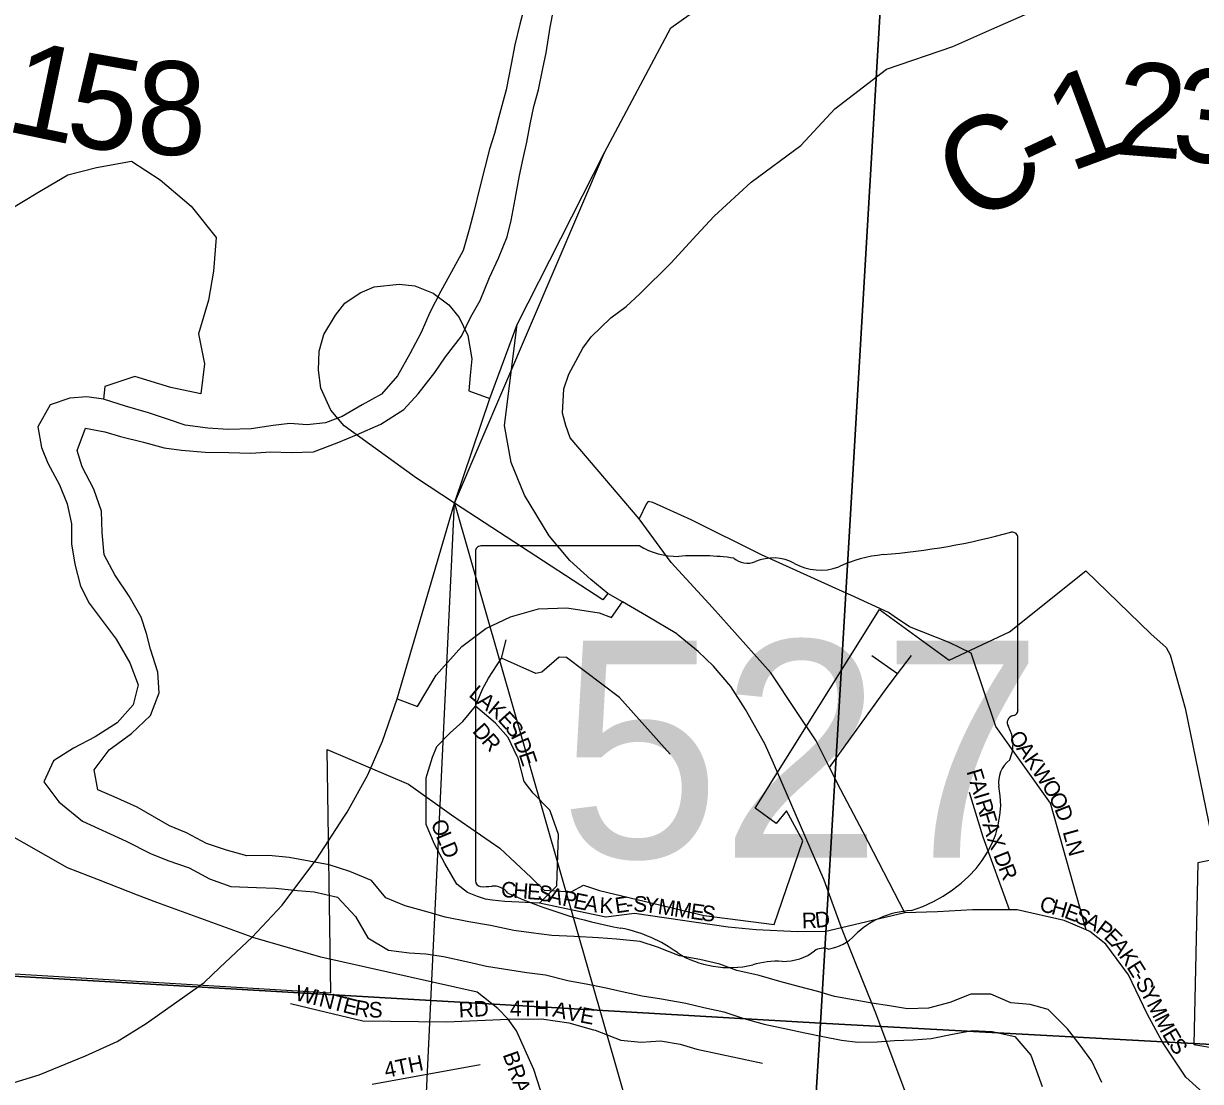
# Model space of a CAD drawing. Extents: x 0 to 34, y 0 to 22.
# Drawn here: x 4.109 to 4.825, y 15.987 to 16.63 of the extents above; entities that cross this region are included whole.
import ezdxf

# ---------------------------------------------------------------- set-up
doc = ezdxf.new("R2010")
doc.units = 0
for name, color, linetype in [('GM_P_State_Alignment', 7, 'Continuous'), ('GM_X_City_Street', 7, 'Continuous'), ('GM_X_City_Street_Text', 7, 'Continuous'), ('GM_X_Corporation', 7, 'Continuous'), ('GM_X_County_Road', 7, 'Continuous'), ('GM_X_County_Road_Text', 7, 'Continuous'), ('GM_X_Interchange_Ramps', 7, 'Continuous'), ('GM_X_Major_River', 7, 'Continuous'), ('GM_X_Minor_River', 7, 'Continuous'), ('GM_X_Section', 7, 'Continuous'), ('GM_X_State_Location', 7, 'Continuous'), ('GM_X_State_Route', 7, 'Continuous'), ('GM_X_State_Shield', 7, 'Continuous'), ('GM_X_Township_Road_Text', 7, 'Continuous'), ('GM_X_Township_Subdivision', 7, 'Continuous'), ('GM_X_Township_Subdivision_Text', 7, 'Continuous'), ('SH_Data', 7, 'Continuous'), ('SH_Text', 7, 'Continuous')]:
    doc.layers.add(name, color=color, linetype=linetype)

msp = doc.modelspace()

# ---------------------------------------------------------------- linework, layer by layer
at = {"layer": 'GM_P_State_Alignment'}
for points in [[(4.40926, 16.44722), (4.46241, 16.55171), (4.50282, 16.62732), (4.55011, 16.66115), (4.59371, 16.69234), (4.64214, 16.7261), (4.67584, 16.73522), (4.75214, 16.75587), (4.84791, 16.82532), (4.91933, 16.86826), (4.9287, 16.87399), (5.03009, 16.93602), (5.04059, 16.93934), (5.06201, 16.94614), (5.20283, 16.99081), (5.21221, 16.99417), (5.27331, 17.01608), (5.30509, 17.02747), (5.3394, 17.03473), (5.52209, 17.10957), (5.54471, 17.11881), (5.5533, 17.1267), (5.65808, 17.22283)], [(4.46447, 16.28377), (4.45404, 16.29219), (4.44126, 16.30382), (4.42886, 16.31873), (4.41378, 16.34348), (4.40578, 16.36333), (4.40157, 16.38581), (4.40926, 16.44722)]]:
    msp.add_lwpolyline(points, dxfattribs=at)
at = {"layer": 'GM_X_City_Street'}
for points in [[(4.75513, 16.07932), (4.73357, 16.15629), (4.70035, 16.20293), (4.68535, 16.24742), (4.67196, 16.25385), (4.64785, 16.2635), (4.63856, 16.2697)], [(4.86125, 15.93632), (4.85274, 15.94797), (4.84833, 15.95944), (4.83245, 15.97489), (4.81569, 15.9899), (4.80157, 16.01108), (4.79231, 16.02829), (4.78084, 16.05212), (4.76716, 16.07066), (4.75735, 16.07837), (4.75513, 16.07932), (4.7419, 16.085), (4.71334, 16.09156), (4.70852, 16.09155), (4.68605, 16.0915), (4.66482, 16.0903), (4.64496, 16.08968), (4.61963, 16.13871), (4.60617, 16.16446), (4.59926, 16.17803), (4.59104, 16.19418), (4.57912, 16.21207)], [(4.60641, 16.08067), (4.59703, 16.07827), (4.57984, 16.07815), (4.5546, 16.07945), (4.53768, 16.08101), (4.4807, 16.08935), (4.4633, 16.08707), (4.43534, 16.09289), (4.42291, 16.09563), (4.40181, 16.09658), (4.39417, 16.09741), (4.39007, 16.09801), (4.38522, 16.09969), (4.3792, 16.10213), (4.37267, 16.10706), (4.36536, 16.11966), (4.35918, 16.13142), (4.35403, 16.14341), (4.35403, 16.16193), (4.35409, 16.17164), (4.35471, 16.17371)], [(4.70852, 16.09155), (4.6926, 16.13576), (4.6843, 16.16278)], [(4.64496, 16.08968), (4.60641, 16.08067)], [(4.44235, 15.92357), (4.41948, 15.9945), (4.4089, 16.0181), (4.4039, 16.02506), (4.39749, 16.03163), (4.38508, 16.04152), (4.29, 16.06275), (4.24872, 16.07468)], [(4.2715, 16.03466), (4.29352, 16.02932), (4.31554, 16.02399), (4.33225, 16.02395), (4.3664, 16.02351), (4.4039, 16.02506)], [(4.4039, 16.02506), (4.42409, 16.02529), (4.44079, 16.02297), (4.45572, 16.01867), (4.4558, 16.01864)], [(4.4558, 16.01864), (4.45672, 16.01838), (4.47227, 16.01227), (4.48479, 16.0111), (4.49656, 16.01184), (4.50832, 16.00991), (4.51856, 16.00685), (4.55839, 15.9984)], [(4.32117, 15.98558), (4.38685, 15.99761)]]:
    msp.add_lwpolyline(points, dxfattribs=at)
at = {"layer": 'GM_X_Corporation'}
msp.add_lwpolyline([(4.05648, 16.05554), (4.29607, 16.04108), (4.29375, 16.18895), (4.34323, 16.16777), (4.36952, 16.14922), (4.39875, 16.12894), (4.41782, 16.11123), (4.42571, 16.10344), (4.44211, 16.1024), (4.44968, 16.10652), (4.45941, 16.10322), (4.5231, 16.08804), (4.56563, 16.08266), (4.58296, 16.13335), (4.57313, 16.15162), (4.56685, 16.14397), (4.55408, 16.15322), (4.62955, 16.27389), (4.67185, 16.24319), (4.70869, 16.26041), (4.75495, 16.29738), (4.79442, 16.25918), (4.80381, 16.25091), (4.80619, 16.24654), (4.81542, 16.21411), (4.8343, 16.12237), (4.82302, 16.12001), (4.82068, 16.00968), (4.84946, 16.00478)], dxfattribs=at)
at = {"layer": 'GM_X_County_Road'}
for points in [[(4.51843, 16.50146), (4.52905, 16.51303), (4.5515, 16.5335), (4.58186, 16.55596), (4.60233, 16.57809), (4.63385, 16.6022), (4.67413, 16.61607), (4.6979, 16.62664), (4.74776, 16.64855), (4.76593, 16.64998), (4.78552, 16.64855), (4.81332, 16.64677), (4.83898, 16.6432)], [(4.45787, 16.35909), (4.44163, 16.37819), (4.43884, 16.38576), (4.43684, 16.39335), (4.43764, 16.4081), (4.44083, 16.41687), (4.4492, 16.43283), (4.45438, 16.43961), (4.46634, 16.45117), (4.47551, 16.45796), (4.48382, 16.4658), (4.50297, 16.48462), (4.51843, 16.50146)], [(4.57912, 16.21207), (4.5635, 16.23552), (4.52812, 16.27524), (4.503, 16.30253), (4.48343, 16.32903), (4.45787, 16.35909)], [(4.35471, 16.17371), (4.3579, 16.18435), (4.36044, 16.1907), (4.36868, 16.19897), (4.3763, 16.20596), (4.38401, 16.21534), (4.38836, 16.22566), (4.39182, 16.2322), (4.39973, 16.24446), (4.40269, 16.25553)], [(4.17849, 16.1005), (4.15495, 16.10967), (4.13596, 16.11707), (4.07143, 16.15377)], [(4.24872, 16.07468), (4.24816, 16.07484), (4.19022, 16.09593), (4.17849, 16.1005)]]:
    msp.add_lwpolyline(points, dxfattribs=at)
at = {"layer": 'GM_X_Interchange_Ramps'}
for points in [[(4.46447, 16.28377), (4.46134, 16.27986), (4.37122, 16.33865), (4.3481, 16.35384), (4.30414, 16.3855), (4.29605, 16.395), (4.29007, 16.40837), (4.28866, 16.41928), (4.28901, 16.43089), (4.29183, 16.44109), (4.29886, 16.45271), (4.30449, 16.46009), (4.31398, 16.46642), (4.32242, 16.46995), (4.33755, 16.47171), (4.34704, 16.47065), (4.35829, 16.46608), (4.36779, 16.45904), (4.37412, 16.4513), (4.3794, 16.44039), (4.38186, 16.42632), (4.38085, 16.41621), (4.37995, 16.40679), (4.39263, 16.40226)], [(4.33649, 16.21965), (4.34874, 16.21506), (4.36005, 16.23403), (4.37561, 16.25152), (4.39021, 16.26237), (4.40524, 16.26947), (4.42235, 16.27448), (4.43946, 16.2749), (4.45908, 16.27198), (4.46673, 16.26908), (4.4734, 16.27855)]]:
    msp.add_lwpolyline(points, dxfattribs=at)
at = {"layer": 'GM_X_Major_River'}
for points in [[(4.41354, 16.63945), (4.41092, 16.62957), (4.40793, 16.61703), (4.40569, 16.60526), (4.40271, 16.58968), (4.39821, 16.57333), (4.39559, 16.56307), (4.39259, 16.55357), (4.3896, 16.54255), (4.38623, 16.52887), (4.38324, 16.51632), (4.38024, 16.50492), (4.3765, 16.492)], [(4.3868, 16.46165), (4.39244, 16.47572), (4.39808, 16.4875), (4.40335, 16.50043), (4.40559, 16.51031), (4.4082, 16.52323), (4.41081, 16.53767), (4.41305, 16.54793), (4.41529, 16.55781), (4.41715, 16.56883), (4.41939, 16.57947), (4.42239, 16.58973), (4.425, 16.60265), (4.42687, 16.61215), (4.42947, 16.62773), (4.43133, 16.63799)], [(4.3765, 16.492), (4.36934, 16.47907), (4.36294, 16.46728), (4.35616, 16.45434), (4.3509, 16.44218), (4.34412, 16.42925), (4.33659, 16.41593), (4.32678, 16.40489), (4.31507, 16.3984), (4.30297, 16.39115), (4.29277, 16.38732), (4.28179, 16.38615), (4.27119, 16.38688), (4.26097, 16.38571), (4.24773, 16.38377), (4.23373, 16.38335), (4.22124, 16.38408), (4.2076, 16.38594), (4.19737, 16.38933), (4.18525, 16.39347), (4.17123, 16.39761), (4.15797, 16.40175), (4.14775, 16.40323), (4.13753, 16.40245), (4.12543, 16.39823), (4.1179, 16.38492), (4.1202, 16.37239), (4.12402, 16.36291), (4.13125, 16.34964), (4.13582, 16.33826), (4.13851, 16.32611), (4.13854, 16.31396), (4.14047, 16.30143), (4.14392, 16.28815), (4.14925, 16.27791), (4.15647, 16.26805), (4.16559, 16.25593), (4.17396, 16.24152), (4.17891, 16.22825), (4.17592, 16.21609), (4.16611, 16.20504), (4.15289, 16.19665), (4.13966, 16.18978), (4.12757, 16.18214), (4.12155, 16.16922), (4.13067, 16.15709), (4.14509, 16.14536), (4.17162, 16.13329), (4.1864, 16.12574), (4.19701, 16.12159), (4.2099, 16.11707), (4.2224, 16.11028), (4.23529, 16.10576), (4.25081, 16.10505), (4.26254, 16.1047), (4.2758, 16.10322), (4.28602, 16.10249), (4.30004, 16.09912), (4.31105, 16.08738), (4.31865, 16.07449), (4.33117, 16.06693), (4.34366, 16.06545), (4.35388, 16.06473), (4.36449, 16.06324), (4.37926, 16.05987), (4.39062, 16.05724), (4.41524, 16.05352), (4.4266, 16.05203), (4.44023, 16.04866), (4.45235, 16.04642), (4.46334, 16.04417), (4.47318, 16.04192), (4.4853, 16.0393), (4.49704, 16.03744), (4.51181, 16.03483), (4.5228, 16.0322), (4.53492, 16.02958), (4.54704, 16.02544), (4.55954, 16.02206), (4.57394, 16.01907), (4.58416, 16.01682), (4.59515, 16.01457), (4.60651, 16.01233), (4.61635, 16.01122), (4.62809, 16.01126), (4.63868, 16.01205), (4.65004, 16.01246), (4.66101, 16.01326), (4.67388, 16.01595), (4.68598, 16.01827), (4.6981, 16.01754), (4.71174, 16.01455), (4.72161, 16.00319), (4.72848, 15.98423)], [(4.76481, 15.98661), (4.75872, 15.9995), (4.7515, 16.00935), (4.7439, 16.0192), (4.73213, 16.03093), (4.72114, 16.03394), (4.70941, 16.03504), (4.69728, 16.04032), (4.68517, 16.04028), (4.67231, 16.03531), (4.65945, 16.03185), (4.64658, 16.03143), (4.6356, 16.0333), (4.62499, 16.03479), (4.61477, 16.03665), (4.60227, 16.03889), (4.59204, 16.0419), (4.5803, 16.0449), (4.56893, 16.04791), (4.55643, 16.05166), (4.5428, 16.05466), (4.53257, 16.05843), (4.52044, 16.06143), (4.50795, 16.06367), (4.49468, 16.06894), (4.48408, 16.07233), (4.46969, 16.0738), (4.45871, 16.07453), (4.44394, 16.07525), (4.43031, 16.07597), (4.41782, 16.07745), (4.40722, 16.07893), (4.3932, 16.08193), (4.37994, 16.08417), (4.36555, 16.08716), (4.35533, 16.09017), (4.34131, 16.09392), (4.32956, 16.09883), (4.32082, 16.10943), (4.30756, 16.11471), (4.29506, 16.11884), (4.27082, 16.12333), (4.25833, 16.12443), (4.24508, 16.12439), (4.23258, 16.12777), (4.22045, 16.13191), (4.20832, 16.13834), (4.19809, 16.14248), (4.17837, 16.15381), (4.16435, 16.16023), (4.1545, 16.16438), (4.15219, 16.17652), (4.16124, 16.1887), (4.17484, 16.19861), (4.18654, 16.20966), (4.1918, 16.22335), (4.191, 16.23588), (4.18642, 16.24991), (4.18412, 16.2594), (4.18069, 16.26927), (4.17346, 16.28216), (4.16472, 16.29505), (4.15825, 16.30718), (4.15707, 16.32085), (4.15665, 16.33376), (4.15207, 16.34704), (4.14484, 16.36069), (4.14179, 16.37055), (4.14704, 16.38424), (4.15878, 16.382), (4.16826, 16.37899), (4.18227, 16.37561), (4.19477, 16.37223), (4.20538, 16.37074), (4.21976, 16.36964), (4.23415, 16.3693), (4.2474, 16.36896), (4.25951, 16.36976), (4.272, 16.36941), (4.28563, 16.36983), (4.29999, 16.37519), (4.31171, 16.38016), (4.32646, 16.38666), (4.34044, 16.39543), (4.34912, 16.40495), (4.3593, 16.41789), (4.36571, 16.42741), (4.37551, 16.43997), (4.38115, 16.45176), (4.3868, 16.46165)]]:
    msp.add_lwpolyline(points, dxfattribs=at)
at = {"layer": 'GM_X_Minor_River'}
msp.add_lwpolyline([(4.10065, 16.51674), (4.11807, 16.52737), (4.13625, 16.538), (4.15367, 16.54255), (4.17488, 16.54634), (4.19227, 16.53493), (4.21118, 16.51896), (4.22629, 16.49995), (4.22475, 16.47943), (4.2217, 16.46195), (4.21561, 16.44144), (4.21937, 16.4232), (4.21708, 16.40496), (4.19891, 16.40877), (4.17697, 16.41562), (4.15879, 16.40955), (4.15797, 16.40175)], dxfattribs=at)
at = {"layer": 'GM_X_Section'}
for points in [[(3.56848, 17.09992), (4.65367, 17.04009), (4.59377, 16.02271), (3.50743, 16.08595)], [(4.65367, 17.04009), (5.72599, 16.97911), (5.67697, 16.13224), (5.6584, 16.12617), (5.62772, 16.11554), (5.59666, 16.1068), (5.53642, 16.08819), (5.51294, 16.07946), (5.48831, 16.06959), (5.4618, 16.05858), (5.43907, 16.05023), (5.42317, 16.04529), (5.40043, 16.03846), (5.37316, 16.03086), (5.308, 16.01262), (5.28868, 16.00617), (5.25686, 15.99478), (5.23679, 15.98757), (4.59377, 16.02271)]]:
    msp.add_lwpolyline(points, close=True, dxfattribs=at)
for points in [[(3.50743, 16.08595), (4.59377, 16.02271), (4.58028, 15.80787), (4.56741, 15.79876), (4.55036, 15.79118), (4.52613, 15.78245), (4.51249, 15.77826), (4.49657, 15.7756), (4.45566, 15.76989), (4.41891, 15.76266), (4.38444, 15.75544), (4.34882, 15.74745), (4.31776, 15.73985), (4.29769, 15.7334), (4.2742, 15.72542), (4.18101, 15.69846), (4.15449, 15.69086), (4.14199, 15.68668), (4.13252, 15.68327), (4.12608, 15.68061), (4.11661, 15.67833), (4.07911, 15.66807)], [(4.8413, 15.87058), (4.81024, 15.86297), (4.7697, 15.85082), (4.70189, 15.83259), (4.67841, 15.82575), (4.65681, 15.81929), (4.64469, 15.81701), (4.62575, 15.81283), (4.59885, 15.80636), (4.58711, 15.80598), (4.58028, 15.80787), (4.59377, 16.02271), (5.23679, 15.98757)]]:
    msp.add_lwpolyline(points, dxfattribs=at)
at = {"layer": 'GM_X_State_Route'}
for points in [[(4.39263, 16.40226), (4.40926, 16.44722)], [(4.3186, 16.17353), (4.32749, 16.19404), (4.33649, 16.21965), (4.37122, 16.33865), (4.37137, 16.33917), (4.39263, 16.40226)], [(4.5072, 16.25847), (4.5063, 16.2592), (4.48788, 16.27011), (4.4734, 16.27855), (4.46447, 16.28377)], [(4.56509, 16.18055), (4.55994, 16.19239), (4.54811, 16.21317), (4.53919, 16.22715), (4.52866, 16.23958), (4.51945, 16.24842), (4.5072, 16.25847)], [(4.64682, 15.97698), (4.62693, 16.02973), (4.60641, 16.08067), (4.59597, 16.10951), (4.56509, 16.18055)], [(4.30388, 16.14773), (4.30595, 16.15094), (4.3184, 16.17308), (4.3186, 16.17353)], [(4.22866, 16.05641), (4.24816, 16.07484), (4.26643, 16.09439), (4.28757, 16.12246), (4.30388, 16.14773)], [(4.08066, 15.98026), (4.09572, 15.98424), (4.11885, 15.99129), (4.14694, 16.00274), (4.16618, 16.01159), (4.18386, 16.02251), (4.21906, 16.04734), (4.22866, 16.05641)]]:
    msp.add_lwpolyline(points, dxfattribs=at)
at = {"layer": 'GM_X_State_Shield'}
for p, q in [((4.48383, 16.31264), (4.38731, 16.31264)), ((4.71364, 16.21291), (4.71364, 16.3176)), ((4.38406, 16.3092), (4.38406, 16.10908)), ((4.71361, 16.21294), (4.71364, 16.21291))]:
    msp.add_line(p, q, dxfattribs=at)
for centre, major_axis, start_param, end_param in [((4.59624, 16.58547), (0.34952, 0), 4.814394, 5.042369), ((4.70999, 16.31803), (0.00367, 0), 6.141152, 7.989035), ((4.38784, 16.30962), (0.00382, 0), 1.712693, 3.28349), ((4.50681, 16.33587), (0.03703, 0), 4.042523, 4.731795), ((4.51909, 16.20029), (0.13295, 0), 1.404758, 1.657858), ((4.54927, 16.31066), (0.01068, 0), 3.836095, 5.185415), ((4.56496, 16.28753), (0.02221, 0), 0.950623, 2.079405), ((4.64082, 16.25152), (0.07032, 0), 1.699011, 2.107814), ((4.59363, 16.31926), (0.02672, 0), 4.081561, 5.145723), ((4.70973, 16.21251), (0.00393, 0), 5.05454, 6.418171), ((4.7128, 16.20523), (0.00568, 0), 1.883978, 3.671073), ((4.67667, 16.192), (0.03409, 0), 5.934695, 6.695948), ((4.72679, 16.16911), (0.0248, 0), 2.387724, 3.262537), ((4.61582, 16.15579), (0.08742, 0), 5.101752, 6.440018), ((4.38787, 16.10864), (0.00385, 0), 3.00124, 4.508301), ((4.38845, 16.12911), (0.0294, 0), 4.665946, 4.897461), ((4.39447, 16.09753), (0.0106, 0), 0.519207, 1.627899), ((4.52829, 16.27733), (0.2524, 0), 4.195997, 4.488961), ((4.65268, 16.05289), (0.04788, 0), 1.647645, 2.488434), ((4.45304, 16.01917), (0.07897, 0), 0.823519, 1.323587), ((4.59202, 16.08968), (0.02824, 0), 4.937069, 5.64225), ((4.59523, 16.06217), (0.00752, 0), 1.147584, 2.315152), ((4.53846, 16.09654), (0.05011, 0), 4.026481, 4.996735), ((4.56741, 16.02735), (0.04118, 0), 1.495662, 1.94098), ((4.57107, 16.08155), (0.0267, 0), 4.691044, 5.507374)]:
    msp.add_ellipse(centre, major_axis=major_axis, ratio=0.8, start_param=start_param, end_param=end_param, dxfattribs=at)
at = {"layer": 'GM_X_Township_Subdivision'}
for points in [[(4.61206, 16.2826), (4.60927, 16.28387), (4.55777, 16.30719), (4.51504, 16.3285), (4.49186, 16.33895), (4.48906, 16.3395), (4.48771, 16.33801), (4.48343, 16.32903)], [(4.63856, 16.2697), (4.63498, 16.27208), (4.61206, 16.2826)], [(4.5024, 16.18613), (4.47156, 16.22054), (4.43925, 16.24485), (4.4349, 16.24505), (4.42443, 16.23595), (4.42067, 16.23516), (4.39973, 16.24446)], [(4.59926, 16.17803), (4.63434, 16.22669), (4.64053, 16.23482), (4.64901, 16.24595)], [(4.64053, 16.23482), (4.62493, 16.24575)], [(4.40936, 16.18468), (4.40383, 16.19612), (4.39625, 16.20486), (4.38401, 16.21534)], [(4.42961, 16.15097), (4.42958, 16.15105), (4.42923, 16.15204), (4.41899, 16.1623), (4.41368, 16.16952), (4.40989, 16.18358), (4.40946, 16.18447), (4.40936, 16.18468)], [(4.42291, 16.09563), (4.4334, 16.10607), (4.43454, 16.13722), (4.42961, 16.15097)]]:
    msp.add_lwpolyline(points, dxfattribs=at)
at = {"layer": 'SH_Data'}
msp.add_lwpolyline([(4.37122, 16.33865), (4.46241, 16.55171), (4.50282, 16.62732), (4.64214, 16.7261), (4.75214, 16.75587), (4.91933, 16.86826), (5.04059, 16.93934), (5.20283, 16.99081), (5.3394, 17.03473), (5.52209, 17.10957), (5.5533, 17.1267), (5.65808, 17.22283), (5.72716, 17.32786), (5.78464, 17.41882), (6.03147, 17.59719)], dxfattribs=at)
at = {"layer": 'SH_Text'}
msp.add_lwpolyline([(4.31689, 15.19549), (4.37122, 16.33865), (4.69914, 15.19549)], close=True, dxfattribs=at)

# ---------------------------------------------------------------- texts
at = {"layer": 'GM_X_City_Street_Text'}
for s, rotation, p in [('O', 304.50615, (4.70767, 16.19635)), ('A', 304.50615, (4.71239, 16.18948)), ('K', 304.50615, (4.71711, 16.18261)), ('F', 286.7668, (4.68238, 16.17557)), ('W', 304.50615, (4.72183, 16.17575)), ('A', 286.73994, (4.68431, 16.16919)), ('O', 301.82826, (4.7279, 16.16692)), ('I', 286.79086, (4.68671, 16.1612)), ('O', 296.47247, (4.73218, 16.16004)), ('R', 286.75188, (4.68791, 16.15721)), ('D', 291.11668, (4.7358, 16.1528)), ('O', 292.70803, (4.35661, 16.14411)), ('F', 286.76655, (4.69007, 16.15003)), ('L', 292.69186, (4.35983, 16.13642)), ('A', 287.24277, (4.69202, 16.14356)), ('LN', 285.52717, (4.74084, 16.13891)), ('D', 292.70309, (4.3624, 16.13027)), ('X', 290.92516, (4.69471, 16.13498)), ('D', 291.50614, (4.69864, 16.12476)), ('R', 291.50969, (4.7017, 16.11701)), ('C', 355.54646, (4.39923, 16.09938)), ('H', 355.54619, (4.4067, 16.0988)), ('E', 355.54603, (4.41501, 16.09815)), ('S', 348.98603, (4.42137, 16.09767)), ('A', 345.33821, (4.42776, 16.09644)), ('P', 347.88614, (4.43627, 16.09422)), ('E', 348.53065, (4.4429, 16.0928)), ('A', 348.65283, (4.44946, 16.09147)), ('K', 357.62352, (4.45923, 16.08963)), ('E', 8.29898, (4.46948, 16.08939)), ('S', 356.28564, (4.47971, 16.09066)), ('Y', 351.97093, (4.48617, 16.09024)), ('M', 351.76782, (4.49442, 16.08908)), ('M', 351.76645, (4.50431, 16.08765)), ('C', 345.11258, (4.72624, 16.09099)), ('H', 344.28544, (4.73345, 16.08908)), ('-', 4.4869, (4.47591, 16.09033)), ('E', 351.77665, (4.51421, 16.08622)), ('S', 351.76874, (4.52081, 16.08526)), ('R', 1.65184, (4.58253, 16.08022)), ('D', 6.79055, (4.59093, 16.0805)), ('E', 339.40239, (4.74127, 16.08689)), ('S', 336.28458, (4.74738, 16.08459)), ('A', 331.81608, (4.75331, 16.082)), ('P', 323.2749, (4.76034, 16.07826)), ('E', 315.20408, (4.76542, 16.0745)), ('A', 306.55049, (4.7699, 16.07009)), ('K', 304.69421, (4.77482, 16.06347)), ('E', 302.11942, (4.7795, 16.05671)), ('S', 297.18444, (4.78491, 16.04758)), ('-', 298.32703, (4.78296, 16.05121)), ('W', 345.78538, (4.27373, 16.03683)), ('I', 345.78358, (4.28424, 16.03417)), ('N', 345.77954, (4.28828, 16.03314)), ('T', 345.78485, (4.29636, 16.0311)), ('Y', 297.0972, (4.78796, 16.04166)), ('E', 345.7832, (4.30282, 16.02946)), ('R', 349.57325, (4.30995, 16.02768)), ('S', 359.16053, (4.31905, 16.02615)), ('RD', 3.01313, (4.37403, 16.02605)), ('4TH', 0.00001, (4.40496, 16.02689)), ('A', 347.13919, (4.43036, 16.02684)), ('V', 348.55222, (4.43874, 16.02493)), ('E', 349.34298, (4.44704, 16.02325)), ('M', 297.10084, (4.79175, 16.03424)), ('M', 297.10067, (4.79631, 16.02533)), ('E', 300.35455, (4.80114, 16.01592)), ('S', 305.31037, (4.805, 16.00941)), ('4TH', 11.76883, (4.32959, 15.98935)), ('BRANCH RD', 289.5156, (4.40044, 16.0036))]:
    msp.add_text(s, height=0.00947, rotation=rotation, dxfattribs=at).set_placement(p)
at = {"layer": 'GM_X_County_Road_Text'}
for s, rotation, p in [('2', 355.46086, (4.77155, 16.55075)), ('1', 20.3121, (4.74513, 16.53949)), ('3', 353.25452, (4.80587, 16.54804)), ('C', 31.57346, (4.68692, 16.50639)), ('-', 25.24184, (4.72522, 16.53004))]:
    msp.add_text(s, height=0.05682, rotation=rotation, dxfattribs=at).set_placement(p)
at = {"layer": 'GM_X_State_Location'}
for s in ['s', 'r']:
    msp.add_text(s, height=0.000189, dxfattribs=at).set_placement((4.54515, 16.19583))
msp.add_text('527', height=0.000189, rotation=0.00001, dxfattribs=at).set_placement((4.47829, 16.18205))
at = {"layer": 'GM_X_State_Shield'}
msp.add_text('527', height=0.131836, dxfattribs=at).set_placement((4.43479, 16.12319))
at = {"layer": 'GM_X_Township_Road_Text'}
for s, rotation, p in [('1', 348.24628, (4.09718, 16.56496)), ('5', 349.94307, (4.13325, 16.55748)), ('8', 359.36943, (4.17785, 16.55042))]:
    msp.add_text(s, height=0.05682, rotation=rotation, dxfattribs=at).set_placement(p)
at = {"layer": 'GM_X_Township_Subdivision_Text'}
for s, rotation, p in [('L', 320.19443, (4.3794, 16.2215)), ('A', 320.18996, (4.38452, 16.21723)), ('K', 320.20108, (4.39093, 16.21189)), ('E', 312.18156, (4.39708, 16.2068)), ('D', 311.207, (4.38167, 16.19983)), ('S', 306.92933, (4.40141, 16.20204)), ('R', 311.38393, (4.38718, 16.19354)), ('I', 296.5052, (4.40517, 16.1971)), ('D', 293.16129, (4.40697, 16.1935)), ('E', 288.60126, (4.41018, 16.18603))]:
    msp.add_text(s, height=0.00947, rotation=rotation, dxfattribs=at).set_placement(p)

doc.saveas('drawing.dxf')
